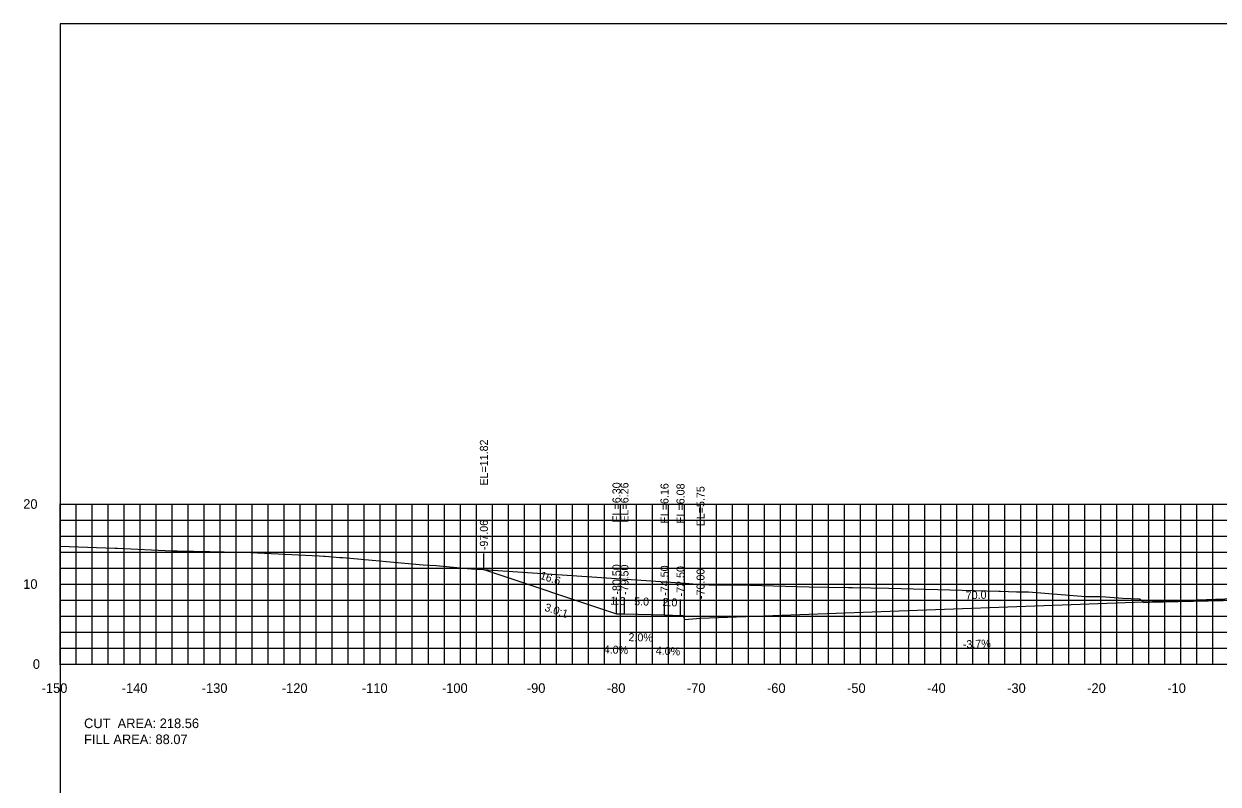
# Model space of a CAD drawing. Extents: x 1797419 to 1809236, y 248759 to 251512.
# Drawn here: x 1805536.5 to 1805685.6, y 250949.9 to 251044.9 of the extents above; entities that cross this region are included whole.
import ezdxf

# ---------------------------------------------------------------- set-up
doc = ezdxf.new("R2010")
doc.units = 0
for name, color, linetype in [('10', 7, 'Continuous'), ('3', 7, 'Continuous'), ('31', 7, 'Continuous'), ('4', 7, 'Continuous'), ('60', 7, 'Continuous'), ('ANNO-TXT', 7, 'Continuous'), ('CL-CNST', 7, 'Continuous'), ('Level 62', 7, 'Continuous'), ('M-ROADS', 7, 'Continuous')]:
    doc.layers.add(name, color=color, linetype=linetype)

msp = doc.modelspace()

# ---------------------------------------------------------------- linework, layer by layer
for p, q in [((1805593.94, 250976.71), (1805593.94, 250978.71)), ((1805610.5, 250971.19), (1805610.5, 250973.19)), ((1805611.5, 250971.15), (1805611.5, 250973.15)), ((1805616.5, 250971.05), (1805616.5, 250973.05)), ((1805618.5, 250970.97), (1805618.5, 250972.97)), ((1805621, 250970.64), (1805621, 250972.64))]:
    msp.add_line(p, q)
msp.add_lwpolyline([(1805541, 250854.89), (1805841, 250854.89), (1805841, 251044.89), (1805541, 251044.89)], close=True)
at = {"layer": '60'}
for p, q in [((1805540.94, 250984.89), (1805541, 250984.89)), ((1805541, 250964.89), (1805541, 250984.89)), ((1805540.94, 250974.89), (1805541, 250974.89)), ((1805540.94, 250964.89), (1805541, 250964.89)), ((1805541, 250964.89), (1805841, 250964.89)), ((1805541, 250964.83), (1805541, 250964.89)), ((1805551, 250964.83), (1805551, 250964.89)), ((1805561, 250964.83), (1805561, 250964.89)), ((1805571, 250964.83), (1805571, 250964.89)), ((1805581, 250964.83), (1805581, 250964.89)), ((1805591, 250964.83), (1805591, 250964.89)), ((1805601, 250964.83), (1805601, 250964.89)), ((1805611, 250964.83), (1805611, 250964.89)), ((1805621, 250964.83), (1805621, 250964.89)), ((1805631, 250964.83), (1805631, 250964.89)), ((1805641, 250964.83), (1805641, 250964.89)), ((1805651, 250964.83), (1805651, 250964.89)), ((1805661, 250964.83), (1805661, 250964.89)), ((1805671, 250964.83), (1805671, 250964.89)), ((1805681, 250964.83), (1805681, 250964.89))]:
    msp.add_line(p, q, dxfattribs=at)
at = {"layer": 'CL-CNST'}
msp.add_lwpolyline([(1805593.94, 250976.71), (1805610.5, 250971.19), (1805611.5, 250971.15), (1805616.5, 250971.05), (1805618.5, 250970.97), (1805618.83, 250970.97), (1805619, 250970.47), (1805621, 250970.64), (1805691, 250973.23), (1805749, 250975.37), (1805751, 250975.21), (1805751.17, 250975.71), (1805751.5, 250975.71), (1805753.5, 250975.79), (1805758.5, 250975.89), (1805759.5, 250975.93), (1805763.19, 250974.7)], dxfattribs=at)
at = {"layer": 'Level 62'}
for p, q in [((1805541, 250984.89), (1805841, 250984.89)), ((1805541, 250964.89), (1805541, 250984.89)), ((1805543, 250964.89), (1805543, 250984.89)), ((1805545, 250964.89), (1805545, 250984.89)), ((1805547, 250964.89), (1805547, 250984.89)), ((1805549, 250964.89), (1805549, 250984.89)), ((1805551, 250964.89), (1805551, 250984.89)), ((1805553, 250964.89), (1805553, 250984.89)), ((1805555, 250964.89), (1805555, 250984.89)), ((1805557, 250964.89), (1805557, 250984.89)), ((1805559, 250964.89), (1805559, 250984.89)), ((1805561, 250964.89), (1805561, 250984.89)), ((1805563, 250964.89), (1805563, 250984.89)), ((1805565, 250964.89), (1805565, 250984.89)), ((1805567, 250964.89), (1805567, 250984.89)), ((1805569, 250964.89), (1805569, 250984.89)), ((1805571, 250964.89), (1805571, 250984.89)), ((1805573, 250964.89), (1805573, 250984.89)), ((1805575, 250964.89), (1805575, 250984.89)), ((1805577, 250964.89), (1805577, 250984.89)), ((1805579, 250964.89), (1805579, 250984.89)), ((1805581, 250964.89), (1805581, 250984.89)), ((1805583, 250964.89), (1805583, 250984.89)), ((1805585, 250964.89), (1805585, 250984.89)), ((1805587, 250964.89), (1805587, 250984.89)), ((1805589, 250964.89), (1805589, 250984.89)), ((1805591, 250964.89), (1805591, 250984.89)), ((1805593, 250964.89), (1805593, 250984.89)), ((1805595, 250964.89), (1805595, 250984.89)), ((1805597, 250964.89), (1805597, 250984.89)), ((1805599, 250964.89), (1805599, 250984.89)), ((1805601, 250964.89), (1805601, 250984.89)), ((1805603, 250964.89), (1805603, 250984.89)), ((1805605, 250964.89), (1805605, 250984.89)), ((1805607, 250964.89), (1805607, 250984.89)), ((1805609, 250964.89), (1805609, 250984.89)), ((1805611, 250964.89), (1805611, 250984.89)), ((1805613, 250964.89), (1805613, 250984.89)), ((1805615, 250964.89), (1805615, 250984.89)), ((1805617, 250964.89), (1805617, 250984.89)), ((1805619, 250964.89), (1805619, 250984.89)), ((1805621, 250964.89), (1805621, 250984.89)), ((1805623, 250964.89), (1805623, 250984.89)), ((1805625, 250964.89), (1805625, 250984.89)), ((1805627, 250964.89), (1805627, 250984.89)), ((1805629, 250964.89), (1805629, 250984.89)), ((1805631, 250964.89), (1805631, 250984.89)), ((1805633, 250964.89), (1805633, 250984.89)), ((1805635, 250964.89), (1805635, 250984.89)), ((1805637, 250964.89), (1805637, 250984.89)), ((1805639, 250964.89), (1805639, 250984.89)), ((1805641, 250964.89), (1805641, 250984.89)), ((1805643, 250964.89), (1805643, 250984.89)), ((1805645, 250964.89), (1805645, 250984.89)), ((1805647, 250964.89), (1805647, 250984.89)), ((1805649, 250964.89), (1805649, 250984.89)), ((1805651, 250964.89), (1805651, 250984.89)), ((1805653, 250964.89), (1805653, 250984.89)), ((1805655, 250964.89), (1805655, 250984.89)), ((1805657, 250964.89), (1805657, 250984.89)), ((1805659, 250964.89), (1805659, 250984.89)), ((1805661, 250964.89), (1805661, 250984.89)), ((1805663, 250964.89), (1805663, 250984.89)), ((1805665, 250964.89), (1805665, 250984.89)), ((1805667, 250964.89), (1805667, 250984.89)), ((1805669, 250964.89), (1805669, 250984.89)), ((1805671, 250964.89), (1805671, 250984.89)), ((1805673, 250964.89), (1805673, 250984.89)), ((1805675, 250964.89), (1805675, 250984.89)), ((1805677, 250964.89), (1805677, 250984.89)), ((1805679, 250964.89), (1805679, 250984.89)), ((1805681, 250964.89), (1805681, 250984.89)), ((1805683, 250964.89), (1805683, 250984.89)), ((1805685, 250964.89), (1805685, 250984.89)), ((1805541, 250982.89), (1805841, 250982.89)), ((1805541, 250980.89), (1805841, 250980.89)), ((1805541, 250978.89), (1805841, 250978.89)), ((1805541, 250976.89), (1805841, 250976.89)), ((1805541, 250974.89), (1805841, 250974.89)), ((1805541, 250972.89), (1805841, 250972.89)), ((1805541, 250970.89), (1805841, 250970.89)), ((1805541, 250968.89), (1805841, 250968.89)), ((1805541, 250966.89), (1805841, 250966.89)), ((1805541, 250964.89), (1805841, 250964.89))]:
    msp.add_line(p, q, dxfattribs=at)
at = {"layer": 'M-ROADS'}
msp.add_lwpolyline([(1805541, 250979.61), (1805547.83, 250979.39), (1805547.99, 250979.39), (1805548.19, 250979.39), (1805554.97, 250979.04), (1805555.42, 250979.04), (1805555.62, 250979.04), (1805559.71, 250978.95), (1805563.27, 250978.88), (1805563.63, 250978.87), (1805563.96, 250978.87), (1805573.38, 250978.4), (1805573.94, 250978.38), (1805574.12, 250978.37), (1805575.94, 250978.22), (1805576.32, 250978.22), (1805586.36, 250977.31), (1805587.96, 250977.19), (1805591.83, 250976.84), (1805591.85, 250976.84), (1805592.39, 250976.79), (1805593.04, 250976.75), (1805593.08, 250976.75), (1805593.83, 250976.72), (1805619.14, 250975), (1805621.38, 250974.81), (1805621.5, 250974.81), (1805621.74, 250974.82), (1805621.86, 250974.82), (1805622.09, 250974.81), (1805627.16, 250974.75), (1805634.58, 250974.54), (1805639.47, 250974.48), (1805639.78, 250974.48), (1805639.98, 250974.48), (1805644.51, 250974.37), (1805658.24, 250973.99), (1805658.45, 250973.99), (1805660.48, 250973.93), (1805660.98, 250973.93), (1805661, 250973.93), (1805661.43, 250973.91), (1805661.44, 250973.91), (1805661.97, 250973.9), (1805669.12, 250973.35), (1805669.29, 250973.35), (1805669.31, 250973.35), (1805671.04, 250973.32), (1805673.19, 250973.17), (1805673.75, 250973.14), (1805675.85, 250973.06), (1805675.97, 250972.97), (1805676.37, 250972.6), (1805676.44, 250972.62), (1805676.44, 250972.62), (1805676.45, 250972.63), (1805676.46, 250972.65), (1805676.47, 250972.65), (1805676.48, 250972.64), (1805676.49, 250972.63), (1805676.5, 250972.63), (1805676.51, 250972.63), (1805676.53, 250972.63), (1805676.53, 250972.63), (1805676.54, 250972.62), (1805676.56, 250972.61), (1805676.57, 250972.6), (1805676.58, 250972.61), (1805676.6, 250972.62), (1805676.63, 250972.64), (1805676.63, 250972.64), (1805676.66, 250972.63), (1805676.69, 250972.62), (1805676.7, 250972.61), (1805676.72, 250972.62), (1805676.76, 250972.62), (1805676.81, 250972.62), (1805676.87, 250972.62), (1805676.93, 250972.61), (1805676.97, 250972.6), (1805677.02, 250972.61), (1805677.11, 250972.62), (1805678.79, 250972.66), (1805690.02, 250972.9)], dxfattribs=at)

# ---------------------------------------------------------------- texts
msp.add_text('3.0:1', height=1, rotation=341.5651).set_placement((1805601.43, 250971.58))
at = {"layer": '10'}
for s, p in [('-150', (1805538.7, 250961.29)), ('-140', (1805548.7, 250961.29)), ('-130', (1805558.7, 250961.29)), ('-120', (1805568.7, 250961.29)), ('-110', (1805578.7, 250961.29)), ('-100', (1805588.7, 250961.29)), ('-90', (1805599.3, 250961.29)), ('-80', (1805609.3, 250961.29)), ('-70', (1805619.3, 250961.29)), ('-60', (1805629.3, 250961.29)), ('-50', (1805639.3, 250961.29)), ('-40', (1805649.3, 250961.29)), ('-30', (1805659.3, 250961.29)), ('-20', (1805669.3, 250961.29)), ('-10', (1805679.3, 250961.29))]:
    msp.add_text(s, height=1.2, dxfattribs=at).set_placement(p)
at = {"layer": '3'}
for s, p in [('EL=11.82', (1805594.44, 250987.19)), ('EL=6.30', (1805611, 250982.58)), ('EL=6.26', (1805612, 250982.57)), ('EL=6.16', (1805617, 250982.47)), ('EL=6.08', (1805619, 250982.44)), ('EL=5.75', (1805621.5, 250982.1)), ('-97.06', (1805594.44, 250979.12)), ('-80.50', (1805611, 250973.57)), ('-79.50', (1805612, 250973.53)), ('-74.50', (1805617, 250973.43)), ('-72.50', (1805619, 250973.35)), ('-70.00', (1805621.5, 250973.02))]:
    msp.add_text(s, height=1, rotation=90, dxfattribs=at).set_placement(p)
at = {"layer": '31'}
for s, p in [('20', (1805536.4, 250984.29)), ('10', (1805536.4, 250974.29)), ('0', (1805537.6, 250964.29))]:
    msp.add_text(s, height=1.2, dxfattribs=at).set_placement(p)
at = {"layer": '4'}
for s, rotation, p in [('16.6', 341.5651, (1805600.86, 250975.57)), ('70.0', 2.119, (1805654.14, 250972.97)), ('1.0', 357.7094, (1805609.73, 250972.32)), ('5.0', 358.8542, (1805612.7, 250972.23)), ('2.0', 357.7094, (1805616.23, 250972.16)), ('2.0%', 358.8542, (1805611.99, 250967.76)), ('-3.7%', 2.119, (1805653.78, 250966.85)), ('4.0%', 357.7094, (1805608.89, 250966.25)), ('4.0%', 357.7094, (1805615.39, 250966.09))]:
    msp.add_text(s, height=1, rotation=rotation, dxfattribs=at).set_placement(p)
at = {"layer": '60'}
msp.add_text('-', height=0.0001, dxfattribs=at).set_placement((1805541, 250964.89))
at = {"layer": 'ANNO-TXT'}
for s, p in [('CUT  AREA: 218.56', (1805544, 250956.89)), ('FILL AREA: 88.07', (1805544, 250954.89))]:
    msp.add_text(s, height=1.2, dxfattribs=at).set_placement(p)

doc.saveas('drawing.dxf')
